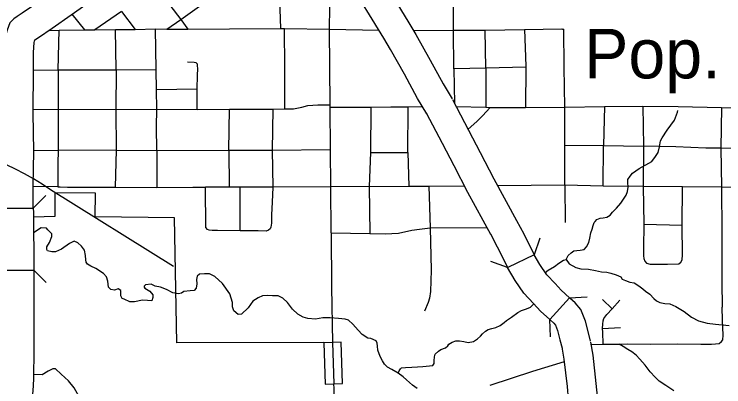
# Model space of a CAD drawing. Extents: x 22866 to 28196, y 1324810 to 1328105.
# Drawn here: x 25775.8 to 25920.9, y 1326082.4 to 1326158.7 of the extents above; entities that cross this region are included whole.
import ezdxf

# ---------------------------------------------------------------- set-up
doc = ezdxf.new("R2010")
doc.units = 0
for name, color, linetype in [('Level 10', 7, 'Continuous'), ('Level 15', 7, 'Continuous'), ('Level 31', 7, 'Continuous'), ('Level 33', 7, 'Continuous'), ('Level 35', 7, 'Continuous'), ('Level 37', 7, 'Continuous'), ('Level 6', 7, 'Continuous'), ('Level 63', 7, 'Continuous')]:
    doc.layers.add(name, color=color, linetype=linetype)

msp = doc.modelspace()

# ---------------------------------------------------------------- linework, layer by layer
at = {"layer": 'Level 10'}
for points in [[(25842.61, 1326177.75), (25844.59, 1326174.95), (25846.97, 1326171.83), (25849.5, 1326168.26), (25853.06, 1326162.58), (25856.5, 1326156.88), (25857.94, 1326154.49), (25860.84, 1326149.3), (25863.52, 1326144.42), (25865.35, 1326141.34)], [(25860.19, 1326138.27), (25858.3, 1326141.44), (25855.59, 1326146.4), (25852.75, 1326151.47), (25851.36, 1326153.78), (25847.94, 1326159.44), (25844.51, 1326164.93), (25842.13, 1326168.28), (25839.75, 1326171.39), (25837.71, 1326174.29)], [(25865.42, 1326141.2), (25868.71, 1326134.96), (25871.07, 1326130.4)], [(25865.74, 1326127.64), (25863.39, 1326132.18), (25860.11, 1326138.41)], [(25871.07, 1326130.4), (25873.88, 1326124.97), (25878.51, 1326116.47)], [(25873.24, 1326113.6), (25868.58, 1326122.15), (25865.74, 1326127.64)], [(25878.52, 1326116.45), (25879.98, 1326113.72), (25882.1, 1326109.43), (25876.7, 1326106.82)], [(25876.7, 1326106.82), (25874.64, 1326110.97), (25873.23, 1326113.63)], [(25889.32, 1326100.65), (25887.66, 1326102.16), (25886.39, 1326103.55), (25884.71, 1326105.33), (25883.27, 1326107.42), (25882.09, 1326109.42)], [(25885.29, 1326096.2), (25883.42, 1326097.91), (25882, 1326099.46), (25880.03, 1326101.55), (25878.22, 1326104.17), (25876.69, 1326106.82)], [(25893.64, 1326091.77), (25893.22, 1326093.48), (25892.64, 1326095.86), (25891.64, 1326098.21), (25890.48, 1326099.61), (25889.38, 1326100.59), (25889.32, 1326100.65), (25885.29, 1326096.2)], [(25885.29, 1326096.2), (25885.36, 1326096.13), (25886.15, 1326095.44), (25886.45, 1326095.06), (25886.92, 1326093.96), (25887.39, 1326092.05), (25887.81, 1326090.33)], [(25895.05, 1326080.47), (25894.8, 1326083.11), (25894.15, 1326088.91), (25893.68, 1326091.57)], [(25887.77, 1326090.53), (25888.21, 1326088.05), (25888.83, 1326082.49), (25889.08, 1326079.91)]]:
    msp.add_lwpolyline(points, dxfattribs=at)
at = {"layer": 'Level 15'}
for points in [[(25787.46, 1326158.56), (25794.65, 1326163.66), (25801.44, 1326168.81), (25808.23, 1326174.13), (25815.22, 1326179.33), (25822.07, 1326184.61)], [(25783.99, 1326163.45), (25780.15, 1326160.72), (25777.46, 1326158.88), (25776.42, 1326158.2), (25775.76, 1326157.76), (25774.93, 1326156.93), (25774.39, 1326155.38), (25773.95, 1326154.04), (25773.76, 1326151.01), (25773.75, 1326147.17), (25773.75, 1326146.63)], [(25779.75, 1326146.61), (25779.75, 1326147.15), (25779.76, 1326150.82), (25779.89, 1326152.89), (25780.06, 1326153.41), (25780.79, 1326153.89), (25783.58, 1326155.8), (25787.46, 1326158.56)], [(25779.73, 1326138.42), (25779.72, 1326139.16), (25779.75, 1326146.61)], [(25773.73, 1326138.37), (25773.81, 1326130.64), (25773.71, 1326123.49), (25773.74, 1326118.96), (25779.74, 1326119.01)], [(25779.74, 1326119.01), (25779.71, 1326123.47), (25779.81, 1326130.63), (25779.73, 1326138.43)], [(25779.74, 1326119.01), (25779.75, 1326118.1), (25779.82, 1326106.32)], [(25771.56, 1326075.39), (25772.86, 1326078.33), (25773.38, 1326080.23), (25773.67, 1326082.13), (25773.76, 1326084.22), (25773.86, 1326090.11), (25773.86, 1326100.2), (25773.82, 1326106.29), (25779.82, 1326106.32)], [(25779.82, 1326106.32), (25779.86, 1326100.21), (25779.86, 1326090.06), (25779.76, 1326084.04), (25779.66, 1326081.55), (25779.26, 1326078.98), (25778.53, 1326076.31), (25777.8, 1326074.67)]]:
    msp.add_lwpolyline(points, dxfattribs=at)
at = {"layer": 'Level 31'}
for p in [(25842.69, 1326091.54), (25839.09, 1326091.42)]:
    msp.add_line(p, (25839.09, 1326091.42), dxfattribs=at)
for points in [[(25839.09, 1326091.42), (25839.37, 1326082.96)], [(25839.37, 1326082.96), (25842.97, 1326083.08), (25842.69, 1326091.54)], [(25840.89, 1326091.48), (25841.17, 1326083.02)]]:
    msp.add_lwpolyline(points, dxfattribs=at)
at = {"layer": 'Level 33'}
for points in [[(25807.04, 1326155.62), (25809.89, 1326157.61), (25817.05, 1326162.79), (25823.79, 1326167.96), (25830.09, 1326172.22)], [(25830.32, 1326155.77), (25830.14, 1326161.73), (25830.17, 1326163.33), (25830.1, 1326170.34)], [(25840.27, 1326155.62), (25840.32, 1326160.11), (25840.2, 1326169.75)], [(25801.5, 1326168.86), (25802.41, 1326167.73), (25804.72, 1326164.42), (25809.89, 1326157.61), (25811.33, 1326155.62)], [(25865.6, 1326155.4), (25865.63, 1326163.89)], [(25787.6, 1326158.66), (25790.17, 1326155.46)], [(25797.79, 1326159.22), (25792.28, 1326155.48)], [(25797.79, 1326159.22), (25800.54, 1326155.55)], [(25782.94, 1326155.36), (25784.99, 1326155.38), (25790.17, 1326155.46), (25792.28, 1326155.48)], [(25784.85, 1326147.29), (25784.99, 1326155.38)], [(25792.28, 1326155.48), (25796.52, 1326155.57), (25800.54, 1326155.55), (25804.74, 1326155.68), (25807.04, 1326155.62), (25811.33, 1326155.62), (25819.85, 1326155.68), (25830.32, 1326155.77), (25831.06, 1326155.78), (25840.27, 1326155.62), (25850.38, 1326155.4)], [(25796.64, 1326147.32), (25796.52, 1326155.57)], [(25804.82, 1326147.37), (25804.74, 1326155.68)], [(25831.15, 1326139.29), (25831.16, 1326147.73), (25831.06, 1326155.78)], [(25840.39, 1326139.57), (25840.39, 1326140.15), (25840.27, 1326155.62)], [(25857.42, 1326155.35), (25865.6, 1326155.4)], [(25865.6, 1326155.4), (25872.1, 1326155.38), (25880.17, 1326155.54), (25887.74, 1326155.65), (25887.89, 1326155.64), (25888.2, 1326155.64)], [(25865.7, 1326147.51), (25865.6, 1326155.4)], [(25872.26, 1326147.64), (25872.1, 1326155.38)], [(25880.17, 1326155.54), (25880.41, 1326148.06), (25880.38, 1326147.83), (25880.35, 1326139.56)], [(25888.27, 1326147.86), (25888.2, 1326155.64)], [(25813.24, 1326143.35), (25813.33, 1326146.19), (25813.37, 1326147.47), (25813.33, 1326148.17), (25813.3, 1326148.45), (25813.01, 1326148.7), (25812.64, 1326148.81), (25811.22, 1326148.86)], [(25880.38, 1326147.83), (25872.26, 1326147.64), (25865.7, 1326147.51)], [(25888.38, 1326139.62), (25888.27, 1326147.86)], [(25779.75, 1326147.21), (25784.85, 1326147.29), (25796.64, 1326147.32), (25804.82, 1326147.37)], [(25784.85, 1326147.29), (25784.83, 1326139.11)], [(25796.64, 1326147.32), (25796.63, 1326139.16)], [(25805, 1326130.79), (25804.91, 1326135.64), (25804.97, 1326139.21), (25804.91, 1326143.17), (25804.82, 1326147.37)], [(25865.7, 1326147.51), (25865.84, 1326140.41)], [(25872.26, 1326147.64), (25872.26, 1326139.64)], [(25813.21, 1326139.2), (25813.24, 1326143.35), (25804.91, 1326143.17)], [(25784.83, 1326139.11), (25779.72, 1326139.14)], [(25796.63, 1326139.16), (25784.83, 1326139.11)], [(25784.83, 1326139.11), (25784.85, 1326130.76)], [(25796.63, 1326139.16), (25804.97, 1326139.21), (25813.21, 1326139.2), (25819.82, 1326139.21), (25828.73, 1326139.23), (25831.15, 1326139.29), (25832.93, 1326139.34), (25834.6, 1326139.68), (25835.83, 1326139.99), (25837.89, 1326140.1), (25840.39, 1326140.15)], [(25796.63, 1326139.16), (25796.69, 1326130.84)], [(25819.71, 1326130.84), (25819.82, 1326139.21)], [(25828.73, 1326139.23), (25828.57, 1326130.86)], [(25859.33, 1326139.73), (25856.39, 1326139.65), (25852.85, 1326139.63), (25848.76, 1326139.61), (25840.39, 1326139.57)], [(25840.52, 1326123.33), (25840.47, 1326130.97), (25840.39, 1326139.57)], [(25848.76, 1326139.61), (25848.67, 1326130.36), (25848.41, 1326123.43)], [(25856.3, 1326130.34), (25856.39, 1326139.65)], [(25866.18, 1326139.76), (25872.26, 1326139.64), (25873.11, 1326139.61), (25880.35, 1326139.56)], [(25868.6, 1326135.17), (25870.42, 1326136.71), (25871.54, 1326137.86), (25873.11, 1326139.61)], [(25880.35, 1326139.56), (25888.38, 1326139.62), (25896.48, 1326139.79), (25904.34, 1326139.83), (25911.56, 1326139.8), (25920.39, 1326139.55)], [(25888.39, 1326123.65), (25888.39, 1326131.84), (25888.38, 1326139.62)], [(25896.48, 1326139.79), (25896.31, 1326131.82)], [(25904.34, 1326139.83), (25904.49, 1326131.69)], [(25920.39, 1326139.55), (25920.28, 1326131.23)], [(25920.39, 1326139.55), (25928.1, 1326139.53), (25928.53, 1326139.52)], [(25888.39, 1326131.84), (25896.31, 1326131.82), (25904.49, 1326131.69)], [(25896.21, 1326123.47), (25896.31, 1326131.82)], [(25796.69, 1326130.84), (25784.85, 1326130.76), (25779.81, 1326130.68)], [(25784.85, 1326130.76), (25784.72, 1326128.12), (25784.72, 1326125.58), (25784.75, 1326123.33)], [(25796.69, 1326130.84), (25796.46, 1326123.26)], [(25796.69, 1326130.84), (25805, 1326130.79), (25819.71, 1326130.84), (25820.14, 1326130.85), (25822.56, 1326130.87), (25828.57, 1326130.86)], [(25805, 1326130.79), (25805.01, 1326123.2)], [(25819.71, 1326130.84), (25819.74, 1326123.25)], [(25828.57, 1326130.86), (25828.68, 1326123.25), (25828.55, 1326120.2), (25828.45, 1326117.64), (25828.42, 1326115.91), (25828.32, 1326115.08), (25828.13, 1326114.73), (25827.79, 1326114.46), (25827.3, 1326114.27), (25825.7, 1326114.32), (25822.04, 1326114.32)], [(25828.57, 1326130.86), (25840.47, 1326130.97)], [(25848.67, 1326130.36), (25856.3, 1326130.34)], [(25856.3, 1326130.34), (25856.48, 1326123.46)], [(25904.49, 1326131.69), (25904.41, 1326123.42)], [(25920.28, 1326131.23), (25917.2, 1326131.27), (25911.08, 1326131.5), (25904.49, 1326131.69)], [(25920.28, 1326131.23), (25920.38, 1326123.26), (25920.49, 1326114.01), (25920.49, 1326106.66), (25920.49, 1326103.83)], [(25968.62, 1326130.29), (25960.57, 1326130.56), (25952.33, 1326130.74), (25944.16, 1326130.96), (25936.5, 1326131.05), (25928.53, 1326131.13), (25920.28, 1326131.23)], [(25784.75, 1326123.33), (25779.71, 1326123.43)], [(25784.75, 1326123.33), (25785.22, 1326123.33), (25786.73, 1326123.25), (25791.57, 1326123.28), (25796.46, 1326123.26), (25805.01, 1326123.2), (25812.35, 1326123.28), (25814.9, 1326123.27)], [(25848.41, 1326123.43), (25840.52, 1326123.33), (25828.68, 1326123.25), (25822.04, 1326123.25), (25819.74, 1326123.25), (25814.9, 1326123.27)], [(25822.04, 1326114.32), (25817.42, 1326114.38), (25816.28, 1326114.41), (25815.71, 1326114.48), (25815.32, 1326114.59), (25815, 1326115.02), (25814.9, 1326123.27)], [(25822.04, 1326114.32), (25822.04, 1326123.25)], [(25840.65, 1326113.9), (25840.52, 1326123.33)], [(25848.41, 1326123.43), (25856.48, 1326123.46)], [(25848.41, 1326123.43), (25848.52, 1326113.76)], [(25856.48, 1326123.46), (25860.59, 1326123.48), (25867.86, 1326123.54)], [(25860.59, 1326123.48), (25860.83, 1326114.92)], [(25888.39, 1326123.65), (25874.64, 1326123.58)], [(25904.41, 1326123.42), (25896.21, 1326123.47), (25888.39, 1326123.65)], [(25888.39, 1326123.65), (25888.47, 1326116.02)], [(25920.38, 1326123.26), (25912.46, 1326123.34), (25904.41, 1326123.42)], [(25904.41, 1326123.42), (25904.5, 1326115.69)], [(25912.38, 1326115.53), (25912.46, 1326123.34)], [(25936.4, 1326122.88), (25928.48, 1326123.1), (25920.38, 1326123.26)], [(25840.65, 1326113.9), (25848.52, 1326113.76), (25851.63, 1326113.71), (25854.37, 1326113.87), (25857.09, 1326114.45), (25858.68, 1326114.71), (25860.83, 1326114.92)], [(25860.83, 1326114.92), (25861.03, 1326106.3), (25860.91, 1326101.92), (25860.71, 1326100.54), (25860.44, 1326099.64), (25859.73, 1326097.9)], [(25860.83, 1326114.92), (25872.47, 1326115.01)], [(25904.5, 1326115.69), (25904.47, 1326110.78), (25904.45, 1326109.2), (25904.55, 1326108.65), (25904.73, 1326108.16), (25905.06, 1326107.74), (25905.85, 1326107.51), (25909.4, 1326107.54), (25911.72, 1326107.6), (25912.13, 1326107.92), (25912.37, 1326108.39), (25912.41, 1326109.4), (25912.38, 1326115.53)], [(25904.5, 1326115.69), (25912.38, 1326115.53)], [(25840.65, 1326113.9), (25840.68, 1326102.84), (25840.89, 1326091.48)], [(25920.49, 1326103.83), (25920.57, 1326098.74)], [(25898.08, 1326098.4), (25896.09, 1326100.31)], [(25896.23, 1326091.13), (25896.15, 1326093.61), (25896.11, 1326094.38), (25896.13, 1326095.21), (25896.19, 1326095.92), (25896.38, 1326096.37), (25896.98, 1326097.19), (25898.08, 1326098.4), (25899.61, 1326100.16)], [(25899.51, 1326091.11), (25901.28, 1326091.18), (25905.85, 1326091.15), (25911.37, 1326091.18), (25916.2, 1326091.13), (25918.35, 1326091.13), (25919.16, 1326091.18), (25919.94, 1326091.31), (25920.44, 1326091.68), (25920.7, 1326092.04), (25920.73, 1326092.96), (25920.62, 1326096.07), (25920.57, 1326098.74)], [(25896.11, 1326094.38), (25899.79, 1326094.58)], [(25893.8, 1326091.09), (25896.23, 1326091.13), (25899.51, 1326091.11)], [(25910.68, 1326081.61), (25909.05, 1326082.66), (25907.69, 1326083.55), (25906.83, 1326084.36), (25905.86, 1326085.46), (25904.81, 1326086.82), (25903.74, 1326088.05), (25902.96, 1326088.91), (25902.07, 1326089.59), (25901.26, 1326090.06), (25900.32, 1326090.64), (25899.51, 1326091.11)], [(25888.26, 1326087.56), (25881.8, 1326085.52), (25873.05, 1326082.68)], [(25841.21, 1326077.16), (25841.2, 1326082.07), (25841.17, 1326083.02)]]:
    msp.add_lwpolyline(points, dxfattribs=at)
at = {"layer": 'Level 35'}
for points in [[(25888.63, 1326108.5), (25889.1, 1326109.26), (25889.68, 1326109.81), (25890.2, 1326110.25), (25890.83, 1326110.33), (25891.51, 1326110.39), (25892.34, 1326110.54), (25892.84, 1326111.07), (25893.31, 1326111.96), (25893.47, 1326112.82), (25893.73, 1326113.92), (25893.96, 1326114.68), (25894.17, 1326115.41), (25894.38, 1326116.01), (25894.57, 1326116.27), (25894.96, 1326116.64), (25895.64, 1326116.9), (25896.21, 1326117), (25896.97, 1326117.14), (25897.65, 1326117.53), (25898.15, 1326118.13), (25898.96, 1326118.99), (25899.82, 1326119.99), (25900.52, 1326121.02), (25900.89, 1326121.64), (25901.2, 1326122.38), (25901.31, 1326123.29), (25901.23, 1326124.26), (25901.23, 1326124.84), (25901.73, 1326125.52), (25902.2, 1326126.17), (25903.55, 1326127.11), (25906.14, 1326128.5), (25906.95, 1326129.52), (25907.48, 1326130.38), (25907.71, 1326131.53), (25907.95, 1326132.79), (25908.29, 1326133.39), (25909.3, 1326134.92), (25910.79, 1326136.96), (25911.44, 1326138.63), (25911.49, 1326138.99)], [(25792.49, 1326106.65), (25791.46, 1326107.1), (25790.78, 1326107.52), (25790.57, 1326107.94), (25790.47, 1326108.41), (25790.42, 1326109.3), (25790.21, 1326110.35), (25789.58, 1326111.18), (25788.85, 1326111.86), (25788.06, 1326112.23), (25787.12, 1326111.76), (25785.5, 1326110.61), (25784.3, 1326110.03), (25783.52, 1326110.03), (25782.63, 1326110.24), (25782.52, 1326110.5), (25782.52, 1326111.03), (25783.04, 1326111.97), (25783.52, 1326113.17), (25783.52, 1326113.75), (25782.73, 1326114.53), (25782.42, 1326114.9), (25781.32, 1326114.95), (25779.77, 1326113.95)], [(25884.37, 1326105.81), (25885, 1326106.27), (25886.28, 1326107.03), (25887.14, 1326107.71), (25888.11, 1326108.34), (25888.63, 1326108.5)], [(25888.63, 1326108.5), (25889.26, 1326107.6), (25890.64, 1326106.84), (25891.66, 1326106.58), (25893.23, 1326106.48), (25894.62, 1326106.24), (25895.87, 1326105.95), (25896.97, 1326105.85), (25897.78, 1326105.69), (25898.88, 1326105.35), (25899.82, 1326104.91), (25900.11, 1326104.46), (25900.76, 1326104.17), (25901.7, 1326103.83), (25902.56, 1326103.7), (25903.52, 1326103.08), (25904.36, 1326102.46), (25904.86, 1326101.98), (25905.77, 1326101.36), (25906.56, 1326100.49), (25907.1, 1326100.02), (25907.78, 1326099.66), (25908.83, 1326099.47), (25909.82, 1326099.37), (25911.08, 1326098.82), (25912.78, 1326097.8), (25914.27, 1326096.67), (25915.73, 1326095.94), (25917.48, 1326095.42), (25919.15, 1326095.21), (25921.95, 1326094.97)], [(25823.64, 1326098.59), (25822.29, 1326097.29), (25821.61, 1326097.18), (25820.72, 1326097.97), (25820.46, 1326098.75), (25820.46, 1326099.69), (25819.94, 1326101.42), (25818.42, 1326103.56), (25816.85, 1326104.98), (25815.75, 1326105.55), (25814.76, 1326105.55), (25813.72, 1326105.45), (25813.25, 1326105.03), (25813.09, 1326104.4), (25813.14, 1326103.46), (25813.04, 1326102.57), (25812.62, 1326102.1), (25811.78, 1326102.05), (25810.53, 1326101.94), (25810, 1326101.58), (25809.38, 1326101.42), (25808.28, 1326101.63), (25806.97, 1326102.36), (25805.72, 1326102.83), (25804.62, 1326102.99), (25803.84, 1326103.41), (25802.69, 1326103.3), (25802.37, 1326103.04), (25802.37, 1326102.78), (25802.53, 1326102.57), (25803.57, 1326102), (25804.15, 1326101.26), (25804.15, 1326100.69), (25803.94, 1326100.01), (25803.05, 1326100.06), (25802.06, 1326100.16), (25800.39, 1326099.8), (25799.44, 1326099.8), (25798.29, 1326100.32), (25797.93, 1326100.48), (25797.61, 1326101.05), (25797.61, 1326101.73), (25797.61, 1326102.15), (25797.09, 1326102.47), (25796.36, 1326102.2), (25795.58, 1326102.31), (25795.11, 1326102.83), (25795, 1326104.04), (25794.69, 1326104.93), (25794.11, 1326105.61), (25792.49, 1326106.65)], [(25855.36, 1326084.44), (25854.3, 1326085.18), (25853.02, 1326085.98), (25852.13, 1326086.45), (25851.55, 1326087.08), (25851.08, 1326087.71), (25850.61, 1326088.6), (25850.14, 1326089.91), (25850.09, 1326090.75), (25850.04, 1326091.32), (25849.83, 1326091.84), (25848.73, 1326092.31), (25848.1, 1326092.37), (25846.95, 1326093.1), (25846.12, 1326094.04), (25845.02, 1326095.25), (25844.18, 1326096.03), (25843.45, 1326096.29), (25842.09, 1326096.4), (25840.42, 1326096.55), (25838.9, 1326096.5), (25837.44, 1326096.24), (25835.82, 1326096.4), (25834.93, 1326096.66), (25833.78, 1326097.29), (25832.73, 1326098.28), (25831.69, 1326099.69), (25830.75, 1326100.53), (25829.81, 1326101), (25829.18, 1326101.05), (25828.66, 1326101.05), (25827.66, 1326101.11), (25826.57, 1326101), (25825.68, 1326100.63), (25824.63, 1326099.95), (25823.64, 1326098.59)], [(25871.58, 1326093.24), (25872.2, 1326093.83), (25872.72, 1326094.17), (25873.45, 1326094.35), (25874.26, 1326094.53), (25875.2, 1326094.93), (25876.01, 1326095.58), (25876.48, 1326096), (25877.48, 1326096.7), (25878.81, 1326097.59), (25879.54, 1326098.04), (25880.54, 1326098.35), (25881.35, 1326098.72), (25882.04, 1326099.41)], [(25854.3, 1326085.18), (25854.53, 1326085.71), (25854.77, 1326086.12), (25855.03, 1326086.28), (25855.81, 1326086.39), (25857.09, 1326086.44), (25858.27, 1326086.52), (25859.37, 1326086.54), (25860.7, 1326086.7), (25861.38, 1326086.75), (25861.67, 1326087.17), (25861.67, 1326087.75), (25861.77, 1326088.53), (25861.9, 1326089.08), (25862.58, 1326089.73), (25863.05, 1326090.07), (25864.02, 1326090.36), (25864.47, 1326090.81), (25864.67, 1326091.17), (25865.35, 1326091.54), (25866.11, 1326091.8), (25866.82, 1326091.83), (25867.73, 1326091.67), (25868.65, 1326091.51), (25869.72, 1326091.72), (25870.53, 1326092.22), (25871.18, 1326092.77), (25871.58, 1326093.24)], [(25790.57, 1326078.55), (25789.89, 1326078.95), (25789.37, 1326079.89), (25788.12, 1326082.2), (25786.91, 1326083.61), (25785.4, 1326085.02), (25784.25, 1326086.07), (25783.72, 1326086.07), (25782.78, 1326085.6), (25781.53, 1326084.86), (25779.78, 1326084.95)], [(25858.19, 1326082.09), (25857.25, 1326082.77), (25855.99, 1326083.81), (25855.36, 1326084.44)]]:
    msp.add_lwpolyline(points, dxfattribs=at)
at = {"layer": 'Level 37'}
for points in [[(25782.27, 1326121.57), (25779.74, 1326119.01)], [(25883.29, 1326112.82), (25882.1, 1326109.42)], [(25876.68, 1326106.83), (25873.29, 1326108.03)], [(25779.82, 1326106.32), (25782.38, 1326103.79)], [(25889.32, 1326100.65), (25892.92, 1326100.82)], [(25885.46, 1326092.61), (25885.29, 1326096.2)]]:
    msp.add_lwpolyline(points, dxfattribs=at)
at = {"layer": 'Level 6'}
msp.add_lwpolyline([(25839.12, 1326091.48), (25809.04, 1326091.42), (25808.59, 1326117.03), (25792.36, 1326117.21), (25792.47, 1326122.07), (25784.12, 1326122.12), (25784.11, 1326117.26), (25779.75, 1326117.13)], dxfattribs=at)
at = {"layer": 'Level 63'}
msp.add_line((25808.38, 1326107.03), (25783.27, 1326122.75), dxfattribs=at)
msp.add_arc((25746.53, 1326068.24), 65.73, 56.0203, 84.902, dxfattribs=at)

# ---------------------------------------------------------------- texts
at = {"layer": 'Level 6'}
msp.add_text('Pop. ', height=10.139, dxfattribs=at).set_placement((25892.33, 1326145.54))

doc.saveas('drawing.dxf')
